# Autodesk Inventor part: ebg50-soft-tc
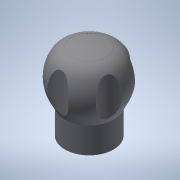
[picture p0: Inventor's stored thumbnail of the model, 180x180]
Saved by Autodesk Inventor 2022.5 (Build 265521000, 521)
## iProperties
Created: 2016-12
Part Number: ebg50-soft-tc
Material: 一般
Document SubType Name: Modeling
Designer: imaocorp
Density: 1 g/cm^3
Appearance: 既定
Author: imaocorp
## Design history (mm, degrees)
node "ebg50-soft-tc.x_t1"
node "ebg50-soft-tc"
node "Base1"
